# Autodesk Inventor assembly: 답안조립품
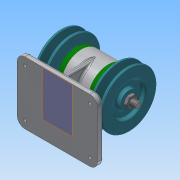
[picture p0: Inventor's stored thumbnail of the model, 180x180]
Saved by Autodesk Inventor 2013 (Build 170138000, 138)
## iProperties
Created: 2019-09
Part Number: 답안조립품
Document SubType Name: Assembly
Designer: Administrator
Author: Administrator
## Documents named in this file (10)
- C:\Users\Administrator\Desktop\490904V1056\답안조립품.iam
- C:\Users\Administrator\Desktop\490904V1056\본체.ipt
- C:\Users\Administrator\Desktop\490904V1056\V-벨트풀리.ipt
- C:\Users\Administrator\Desktop\490904V1056\너트 M10x1.ipt
- C:\Users\Administrator\Desktop\490904V1056\베어링 6004.ipt
- C:\Users\Administrator\Desktop\490904V1056\볼트 M4.ipt
- C:\Users\Administrator\Desktop\490904V1056\오일 실 17 30 5.ipt
- C:\Users\Administrator\Desktop\490904V1056\축.ipt
- C:\Users\Administrator\Desktop\490904V1056\커버.ipt
- C:\Users\Administrator\Desktop\490904V1056\키 5 x 5 x 12.ipt
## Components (2 placed, 1 different names)
1. V-벨트풀리:1
2. V-벨트풀리:2
